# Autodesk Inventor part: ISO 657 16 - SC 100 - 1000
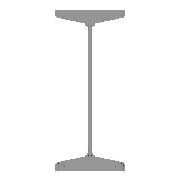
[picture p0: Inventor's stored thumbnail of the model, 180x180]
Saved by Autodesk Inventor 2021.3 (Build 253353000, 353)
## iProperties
IsCustomPart: 1
_CCFamilyMember: 1
_CCFamilyDisplayName: ISO 657/16 - 1980 - Poutres en acier laminées à chaud - Partie 16: profilés en H (série métrique) - Cotes et propriétés de section
_FrameMemberDoc: Frame Member File
_Version: 25.0.0
_GetPNFromCC: 1
Created: 2018-07
Part Number: ISO 657 16 - SC 100 - 1000
Material: Acier, doux
Description: Poutres en acier laminées à chaud - Partie 16: profilés en H (série métrique) - Cotes et propriétés de section
Document SubType Name: Modeling
Standard: ISO
Designer: Fabian Perrée
Standard Revision: First edition 1980-02-15
Standards Organization: ISO
Language: fr-FR
Size Designation: SC 100
Categories: <MemberInstance><Categories><Category DisplayName="Profilés" InternalName="089c4875-fa83-4c05-b084-43b9cc11f5ed" Mnemonic="GRDR"><CategoryParameter DisplayName=
Stock Number: SC 100
Density: 7.85 g/cm^3
Appearance: Semi-poli
Mass: 18568.7 g
Surface Area: 5212.93 cm^2
Volume: 2365.44 cm^3
G_W: 100,000 mm
G_H: 100,000 mm
G_L: 1000,000 mm
+0FF60940-F4FF-4C86-8406-4262D265074C+DETAILDECOUPE7: Grugeage
+041294D9-D90F-4F3A-86FE-30375D234781+DETAILDECOUPE8: Grugeage
Author: Fabian Perrée
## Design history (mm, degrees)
node "Plan de départ"
node "Plan de fin"
sketch "Esquisse"
  geometry: L1 (-3, 0)-(-3, -26.266); L2 (-13.33, -38.149)-(-44.835, -42.577); L3 (-50, -48.518)-(-50, -50); L4 (-50, -50)-(0, -50); L5 (-26.5, -50)-(-26.5, -40); L6 (-61.333, 0)-(81.777, 0); L7 (0, 0)-(0, -50); L8 (0, -60)-(0, 80); L9 (3, 0)-(3, -26.266); L10 (13.33, -38.149)-(44.835, -42.577); L11 (50, -48.518)-(50, -50); L12 (50, -50)-(0, -50); L13 (-3, 0)-(0, 0); L14 (-3, 0)-(-3, 26.266); L15 (-13.33, 38.149)-(-44.835, 42.577); L16 (-50, 48.518)-(-50, 50); L17 (-50, 50)-(0, 50); L18 (50, 48.518)-(50, 50); L19 (13.33, 38.149)-(44.835, 42.577); L20 (3, 0)-(3, 26.266); L21 (50, 50)-(0, 50); L22 (0, 108)-(0, -88) reference; L23 (-89.955, 0)-(110.399, 0) reference; A1 r 6 centre (-44, 48.518) between (-50, 48.518) and (-44.835, 42.577); A2 r 6 centre (44, 48.518) between (44.835, 42.577) and (50, 48.518); A3 r 6 centre (44, -48.518) between (50, -48.518) and (44.835, -42.577); A4 r 6 centre (-44, -48.518) between (-44.835, -42.577) and (-50, -48.518); A5 r 12 centre (-15, 26.266) between (-3, 26.266) and (-13.33, 38.149); A6 r 12 centre (15, 26.266) between (13.33, 38.149) and (3, 26.266); A7 r 12 centre (15, -26.266) between (3, -26.266) and (13.33, -38.149); A8 r 12 centre (-15, -26.266) between (-13.33, -38.149) and (-3, -26.266); 14 further points
  constraints: 42 end point, 24 point on line, 17 symmetric about line, 16 point on circle, 16 tangent, 8 centre point, 6 equal radius, 4 collinear, 2 perpendicular, 12 other
  dimensions: "d1" = 10 vertical distance of L3.end L5.end (= G_T1); "d2" = 23.5 distance between parallel lines of L5 L3 (= -0.25 x G_T + 0.25 x G_W); "d3" = 3 distance between parallel lines of L1 L7 (= 0.5 x G_T); "d4" = 50 distance between parallel lines of L7 L3 (= 0.5 x G_W); "d9" = 50 distance from line of L1.start L4 (= 0.5 x G_H); "d14" = 98 deg angle of L2 L1 (= G_NG); "d15" = 6 radius of A1 (= G_ER); "d16" = 12 radius of A5 (= G_IR)
extrude "Corps" new body sketch "Esquisse" stored distance "d5" = 1000 (= G_L); taper "d6" = 0 deg
node "Driven Length"
  sketch "Sketch3"
    geometry: L1 (0, 0)-(10, 0) reference
    constraints: 2 end point, 1 horizontal
  workplane "Work Plane3"
  sketch "Sketch4"
    geometry: L1 (-2, 0)-(12, 0) reference; L2 (-2, 1000)-(12, 1000) reference
    dimensions: "d20" = 1000 distance between parallel lines of L1 L2 (derived)
node "Plan de construction12"
node "Plan de construction13"
node "Plan de construction14"
sketch "Esquisse5"
  geometry: L1 (-3, 0)-(-3, -26.266); L2 (-13.33, -38.149)-(-44.835, -42.577); L3 (-50, -48.518)-(-50, -50); L4 (-50, -50)-(0, -50); L5 (50, -50)-(0, -50); L6 (50, -48.518)-(50, -50); L7 (13.33, -38.149)-(44.835, -42.577); L8 (3, 0)-(3, -26.266); L9 (3, 0)-(3, 26.266); L10 (13.33, 38.149)-(44.835, 42.577); L11 (50, 48.518)-(50, 50); L12 (50, 50)-(0, 50); L13 (-50, 50)-(0, 50); L14 (-50, 48.518)-(-50, 50); L15 (-13.33, 38.149)-(-44.835, 42.577); L16 (-3, 0)-(-3, 26.266); A1 r 12 centre (-15, -26.266) between (-13.33, -38.149) and (-3, -26.266); A2 r 6 centre (-44, -48.518) between (-44.835, -42.577) and (-50, -48.518); A3 r 6 centre (44, -48.518) between (50, -48.518) and (44.835, -42.577); A4 r 12 centre (15, -26.266) between (3, -26.266) and (13.33, -38.149); A5 r 12 centre (15, 26.266) between (13.33, 38.149) and (3, 26.266); A6 r 6 centre (44, 48.518) between (44.835, 42.577) and (50, 48.518); A7 r 6 centre (-44, 48.518) between (-50, 48.518) and (-44.835, 42.577); A8 r 12 centre (-15, 26.266) between (-3, 26.266) and (-13.33, 38.149)
  constraints: 32 end point, 16 point on circle, 8 centre point
extrude "Extrusion2" cut sketch "Esquisse5" stored distance "d21" = 0.13; taper "d22" = 0 deg
node "Plan de construction15"
node "Plan de construction16"
node "Plan de construction17"
sketch "Esquisse6"
  geometry: L1 (-3, 0)-(-3, -26.266); L2 (-13.33, -38.149)-(-44.835, -42.577); L3 (-50, -48.518)-(-50, -50); L4 (-50, -50)-(0, -50); L5 (50, -50)-(0, -50); L6 (50, -48.518)-(50, -50); L7 (13.33, -38.149)-(44.835, -42.577); L8 (3, 0)-(3, -26.266); L9 (3, 0)-(3, 26.266); L10 (13.33, 38.149)-(44.835, 42.577); L11 (50, 48.518)-(50, 50); L12 (50, 50)-(0, 50); L13 (-50, 50)-(0, 50); L14 (-50, 48.518)-(-50, 50); L15 (-13.33, 38.149)-(-44.835, 42.577); L16 (-3, 0)-(-3, 26.266); A1 r 12 centre (-15, -26.266) between (-13.33, -38.149) and (-3, -26.266); A2 r 6 centre (-44, -48.518) between (-44.835, -42.577) and (-50, -48.518); A3 r 6 centre (44, -48.518) between (50, -48.518) and (44.835, -42.577); A4 r 12 centre (15, -26.266) between (3, -26.266) and (13.33, -38.149); A5 r 12 centre (15, 26.266) between (13.33, 38.149) and (3, 26.266); A6 r 6 centre (44, 48.518) between (44.835, 42.577) and (50, 48.518); A7 r 6 centre (-44, 48.518) between (-50, 48.518) and (-44.835, 42.577); A8 r 12 centre (-15, 26.266) between (-3, 26.266) and (-13.33, 38.149)
  constraints: 32 end point, 16 point on circle, 8 centre point
extrude "Extrusion3" cut sketch "Esquisse6" stored distance "d23" = 0.13; taper "d24" = 0 deg
body "Solid1"
other parameters: "G_W" = 100 (= G_H) [user parameter; used in 2 equation terms], "G_H" = 100 [user parameter; used in 2 equation terms], "G_T" = 6 [user parameter; used in 2 equation terms], "G_T1" = 10 [user parameter; used in 1 equation term], "G_L" = 1000 (= d20) [user parameter; used in 1 equation term], "G_ER" = 6 [user parameter; used in 1 equation term], "G_IR" = 12 [user parameter; used in 1 equation term], "G_NG" = 98 deg [user parameter; used in 1 equation term], "G_OFFSET_START" = 0 [user parameter; used in 1 equation term], "G_OFFSET_END" = 0 [user parameter; used in 1 equation term], "d17" = 0 (computed from G_OFFSET_START), "d19" = 90 deg
